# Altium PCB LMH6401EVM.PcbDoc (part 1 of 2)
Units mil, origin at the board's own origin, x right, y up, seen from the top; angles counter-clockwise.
Board outline 1307 x 2660 mil, 6 copper layers (Top Layer L1, Layer 2 GND L2, Layer 3 V+ L3, Layer 4 V- L4, Layer 5 GND L5, Bottom Layer L6), stack 56.6 mil thick; 69 components, 33 nets, 203 pads, 373 vias.
Unrouted connection lines stored in the file: 2.
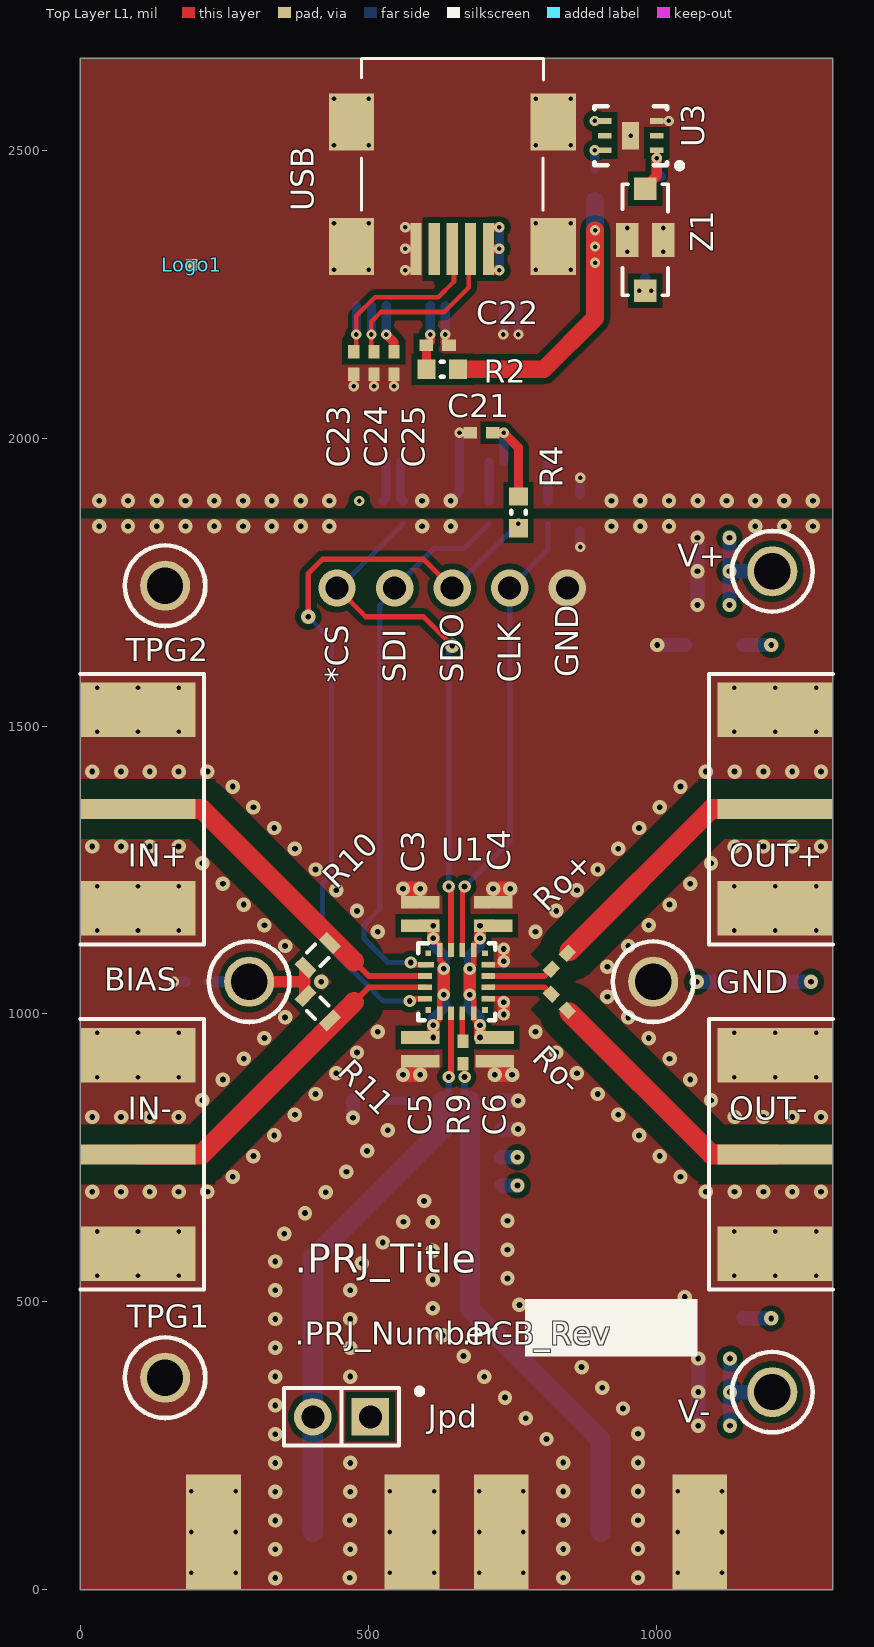
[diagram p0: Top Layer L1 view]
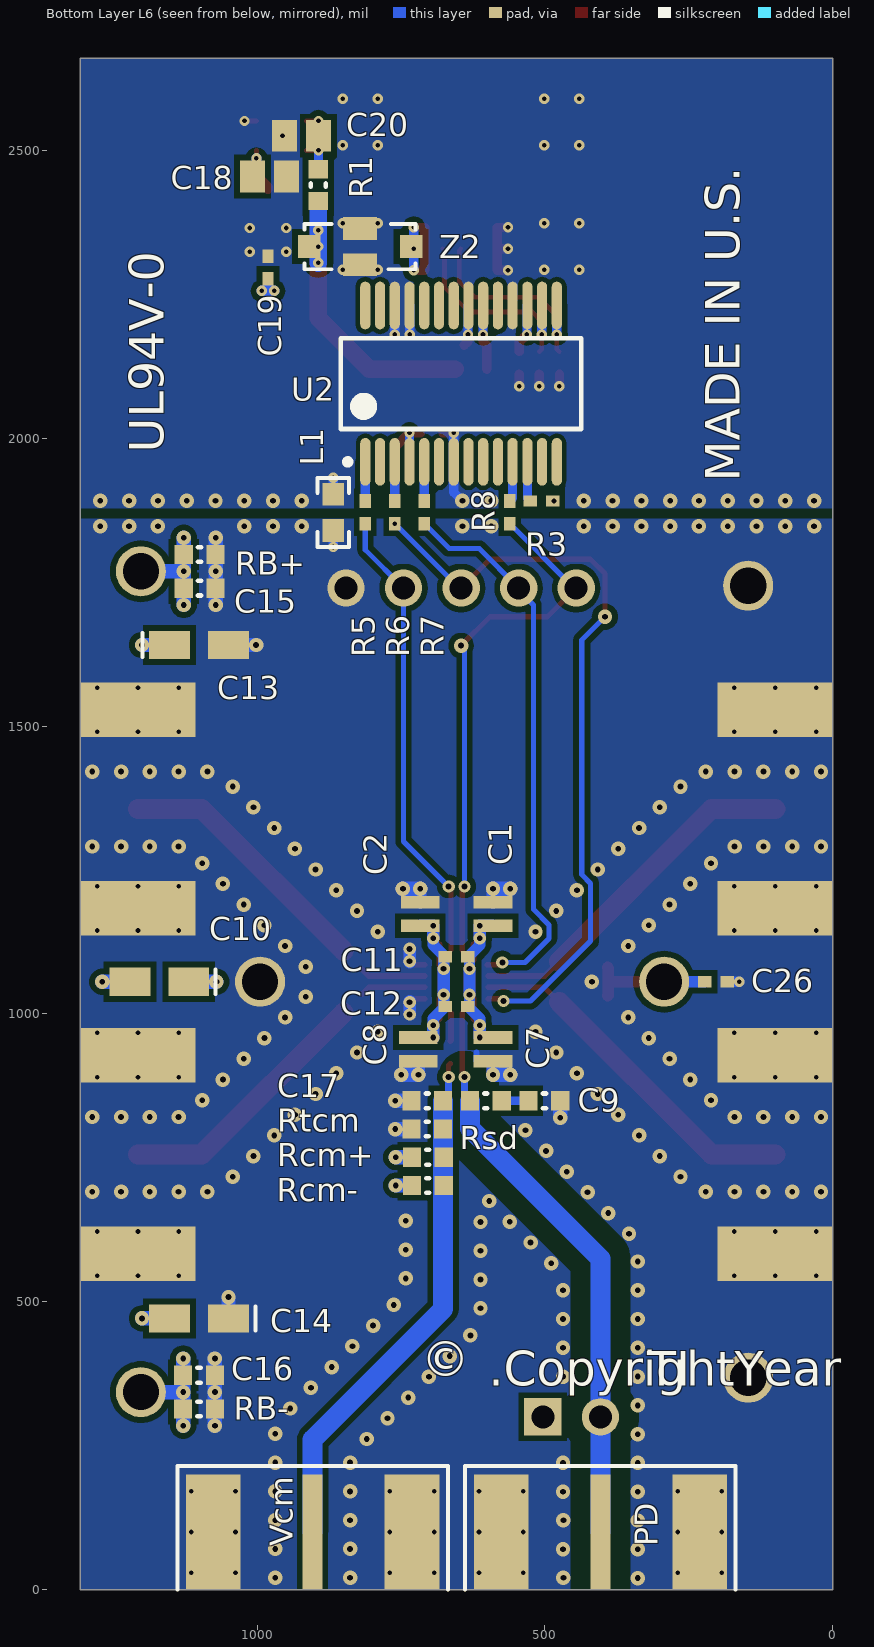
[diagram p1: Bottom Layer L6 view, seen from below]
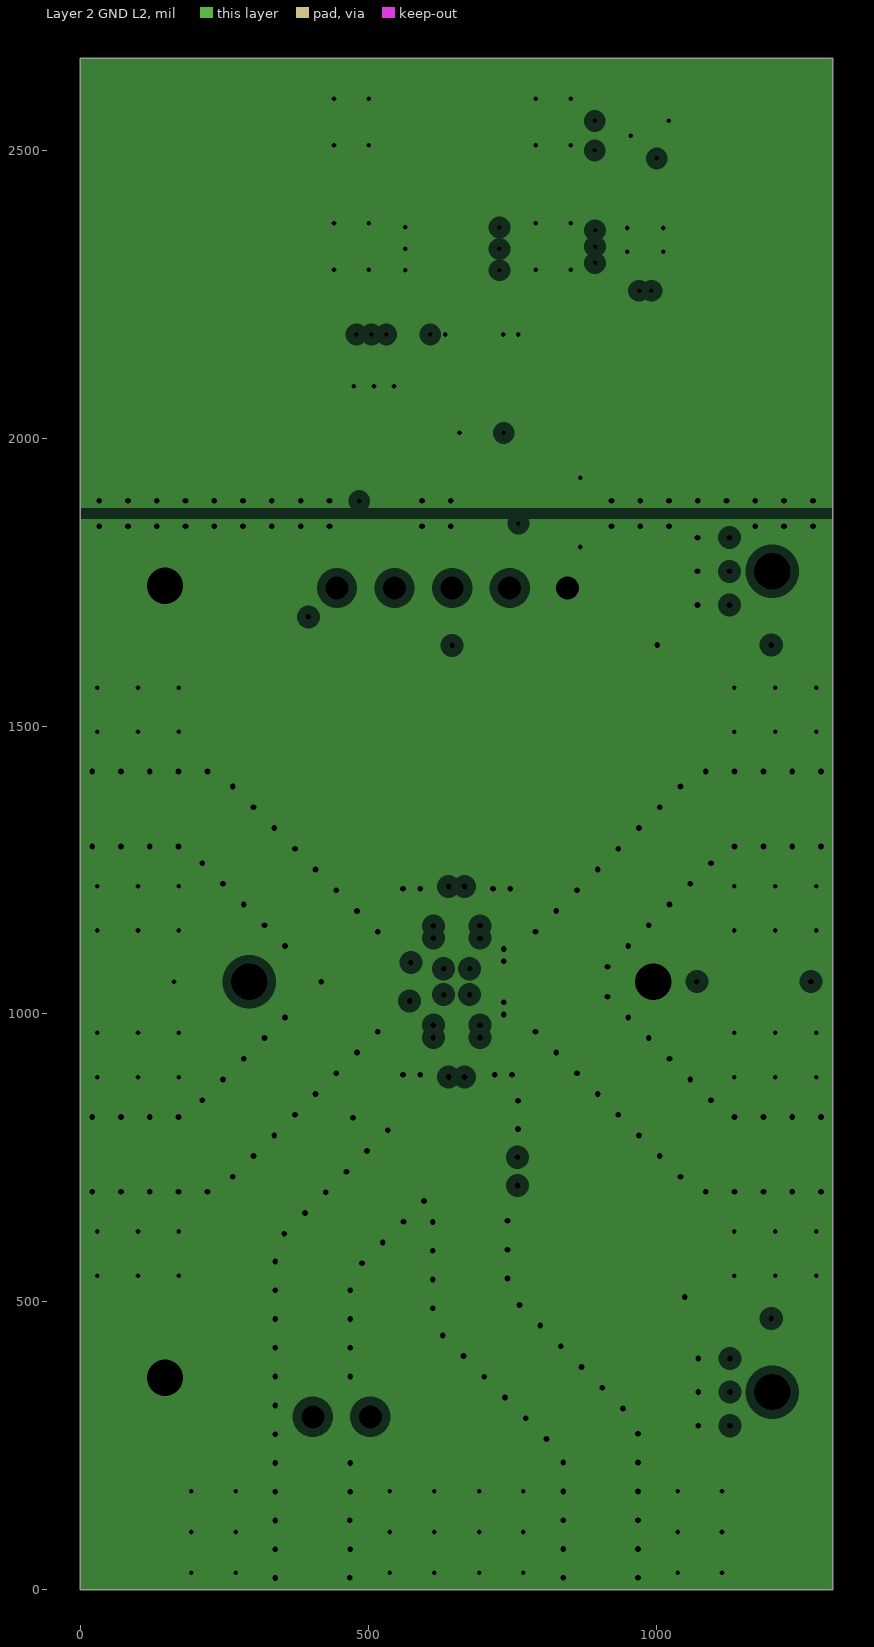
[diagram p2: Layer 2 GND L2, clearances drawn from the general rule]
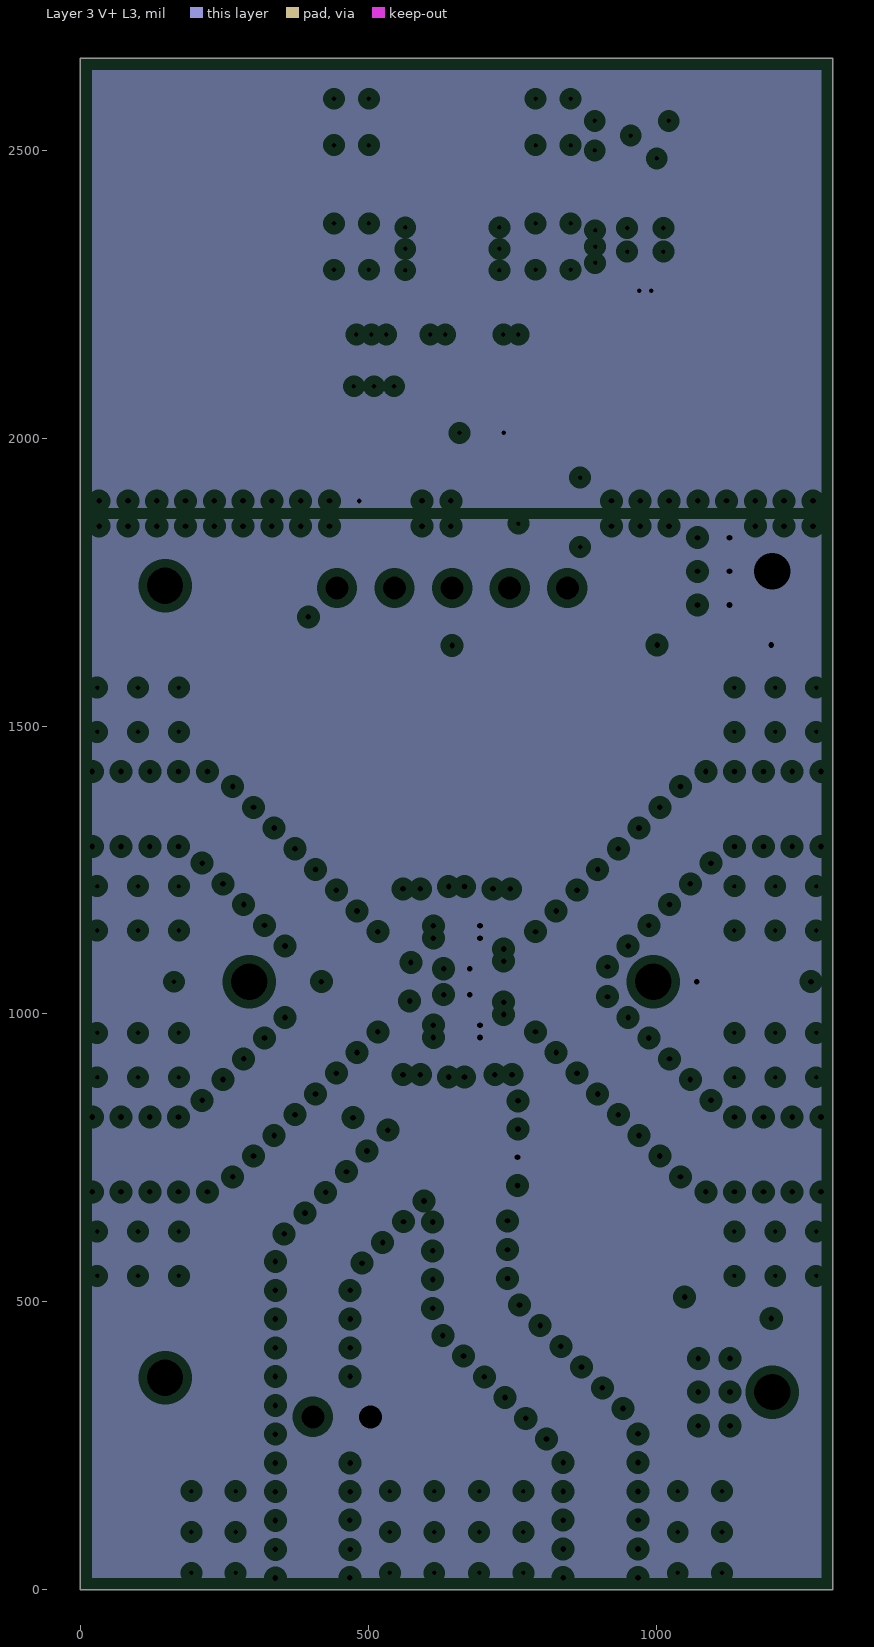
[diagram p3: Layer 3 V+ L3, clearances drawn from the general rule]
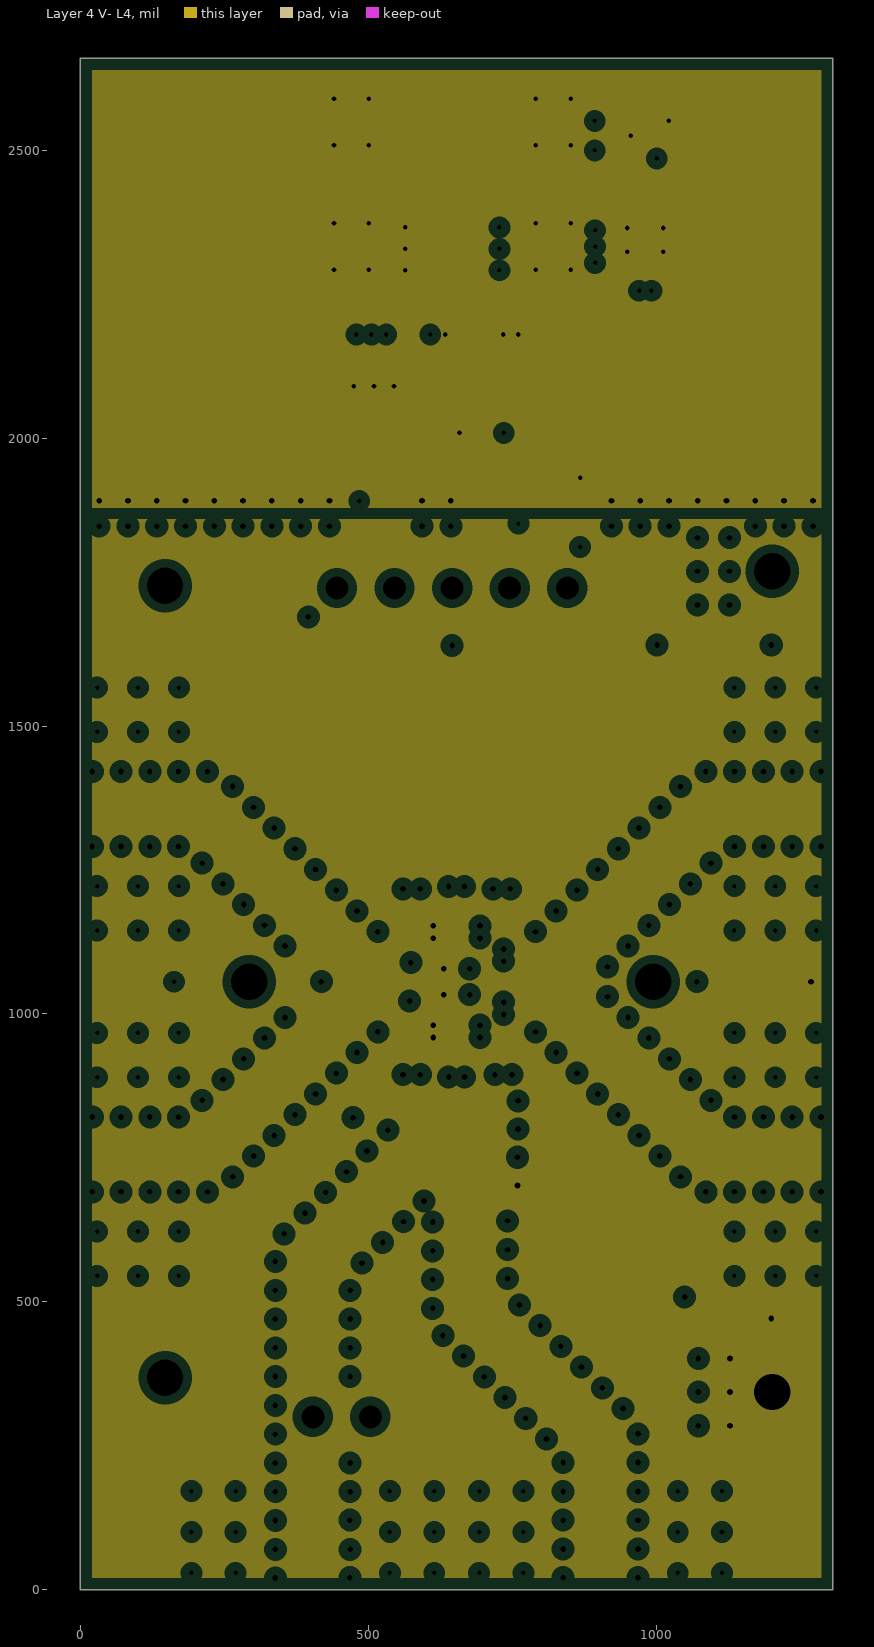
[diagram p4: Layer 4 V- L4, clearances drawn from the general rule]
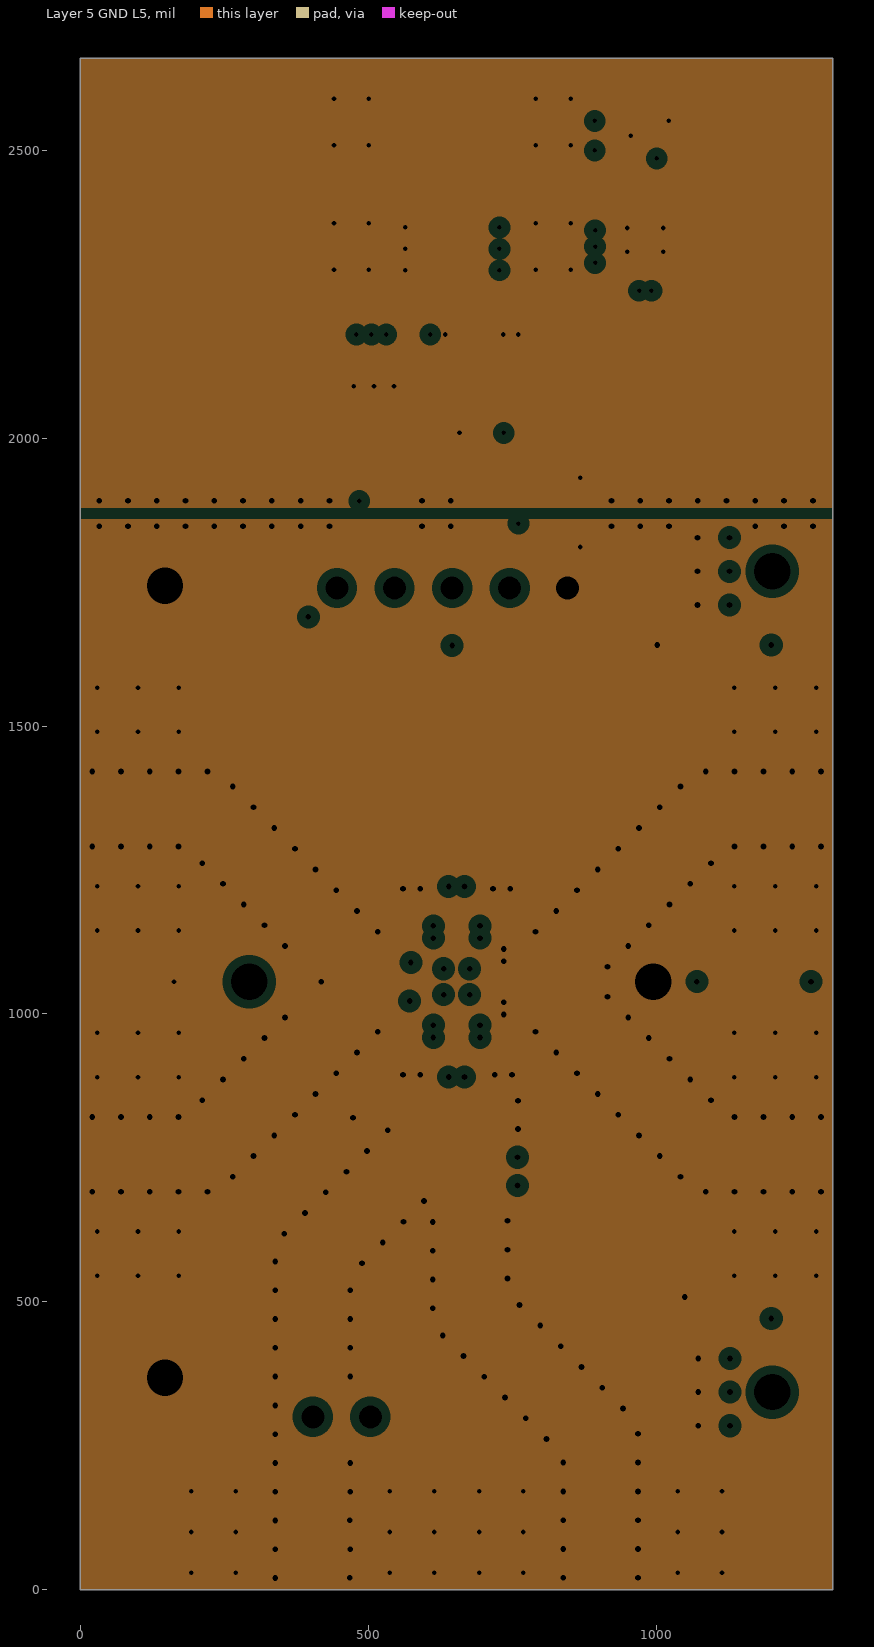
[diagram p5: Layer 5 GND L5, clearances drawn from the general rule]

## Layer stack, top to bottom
Top Layer L1: signal copper 1.4
Dielectric: core 16.6, Rogers RO4350, Dk 3.66
Layer 2 GND L2: plane copper 1.4, net (Multiple Nets)
Dielectric: prepreg 5, FR406, Dk 4.8
Layer 3 V+ L3: plane copper 1.4, net (Multiple Nets)
Dielectric: core 5, FR406, Dk 4.8
Layer 4 V- L4: plane copper 1.4, net (Multiple Nets)
Dielectric: prepreg 5, FR406, Dk 4.8
Layer 5 GND L5: plane copper 1.4, net (Multiple Nets)
Dielectric: core 16.6, FR406, Dk 4.8
Bottom Layer L6: signal copper 1.4

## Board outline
0,0 1307,0 1307,2660 0,2660

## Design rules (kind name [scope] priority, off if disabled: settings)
AcuteAngle [All] p1: minimum=4.50000000000000E+0001 checktracksonly=FALSE
AssemblyTestPointUsage [All] p1: valid=2
Clearance Clearance_2 [(InNamedPolygon('Bottom Layer L6-GND')) vs InNet('NetJpd_2')] p1: gap=35
Clearance Clearance_1 [InNamedPolygon('Top Layer L1-GND') vs (InNet('NetIN+_1') OR InNet('NetIN-_1') OR InNet('NetOUT-_1') OR InNet('NetOUT+_1') OR InNet('NetRtcm_1'))] p2: gap=35
Clearance Clearance_U2 [InComponent('U2')] p3: gap=7.87
Clearance Clearance_BoardEdge_MountingHoles [OnCopper and InComponentClass('Mounting Holes') vs IsKeepOut] p4: gap=40
Clearance Clearance_BoardEdge_Poly [OnCopper and InPoly vs IsKeepOut] p5: gap=25
Clearance Clearance_BoardEdge [OnCopper and Not InComponentClass('Logo') and not InComponentClass('FiducialMark') and not InRegion(1000,500,4000,800) and Not IsKeepout vs IsKeepOut] p6: gap=75
Clearance Clearance_Poly [InPolygon] p7: gap=10
Clearance [All] p8: gap=5
ComponentClearance ComponentClearance_1 [HasFootprint ('Emerson_142-0701-851*') or HasFootprint ('Keystone_1902C*') or HasFootprint ('NY PMS 440 0025 PH*') or HasFootprint ('Fiducial10-20*') vs HasFootprint ('Emerson_142-0701-851*') or HasFootprint ('Keystone_1902C*') or HasFootprint ('NY PMS 440 0025 PH*') or HasFootprint ('Fiducial10-20*')] p1: gap=0 collisioncheckmode=3 verticalgap=10 showdistances=FALSE
ComponentClearance ComponentClearance_Shunt [InComponentClass('Header') vs InComponentClass('Shunt')] p2: gap=0 collisioncheckmode=3 verticalgap=0 showdistances=FALSE
ComponentClearance ComponentClearance_Logo [InComponentClass('Logo')] p3: gap=50 collisioncheckmode=3 verticalgap=10 showdistances=FALSE
ComponentClearance ComponentClearance_ScrewToNut [(HasFootprint('NY PMS 440 0025 PH')) vs (HasFootprint('Keystone_1902C'))] p4: gap=5 collisioncheckmode=3 verticalgap=10 showdistances=FALSE
ComponentClearance ComponentClearance_MountingHoles [InComponentClass('Mounting Holes')] p5: gap=250 collisioncheckmode=3 verticalgap=100000 showdistances=FALSE
ComponentClearance ComponentClearance_SmallPassives [HasFootprint('0201*') or HasFootprint('0402*') or HasFootprint('0508') or HasFootprint('0603*') or HasFootprint('0612') or HasFootprint('0805*') or HasFootprint('0815*') or HasFootprint('0830*') or HasFootprint('1206*') or HasFootprint('1210*') or HasFootprint('1808*') or HasFootprint('1812*') or HasFootprint('1825*') or HasFootprint('2010*') or HasFootprint('2220*') or HasFootprint('2225*') or HasFootprint('2512*') or HasFootprint('2728*') or HasFootprint('3518*') or HasFootprint('FIL_NFM41P*') or HasFootprint('SDB06A*') or HasFootprint('0306*') or HasFootprint('RMZ0016A*') vs HasFootprint('0201*') or HasFootprint('0402*') or HasFootprint('0508') or HasFootprint('0603*') or HasFootprint('0612') or HasFootprint('0805*') or HasFootprint('0815*') or HasFootprint('0830*') or HasFootprint('1206*') or HasFootprint('1210*') or HasFootprint('1808*') or HasFootprint('1812*') or HasFootprint('1825*') or HasFootprint('2010*') or HasFootprint('2220*') or HasFootprint('2225*') or HasFootprint('2512*') or HasFootprint('2728*') or HasFootprint('3518*') or HasFootprint('FIL_NFM41P*') or HasFootprint('SDB06A*') or HasFootprint('0306*') or HasFootprint('RMZ0016A*')] p6: gap=10 collisioncheckmode=3 verticalgap=10 showdistances=FALSE
ComponentClearance ComponentClearance_THtoSMT [IsThruComponent vs IsSMTComponent] p7: gap=10 collisioncheckmode=3 verticalgap=0 showdistances=FALSE
ComponentClearance ComponentClearance_THtoTH [IsThruComponent vs IsThruComponent] p8: gap=75 collisioncheckmode=3 verticalgap=30 showdistances=FALSE
ComponentClearance [All] p9: gap=40 collisioncheckmode=3 verticalgap=10 showdistances=FALSE
DiffPairsRouting [All] p1: maxlimit=100 minlimit=10 mostfreqgap=10 maxuncoupledlength=1000
FabricationTestPointUsage TestPointUsage [All] p1: valid=2 allowmultiple=FALSE
FabricationTestpoint Testpoint [All] p1: side=3 testpointundercomponent=TRUE minsize=40 maxsize=100 preferedsize=60 minholesize=0 maxholesize=40 preferedholesize=32 testpointgrid=1 allowsidetop=TRUE allowsidebottom=TRUE usegrid=TRUE gridtolerance=0.01
FanoutControl Fanout_LCC [IsLCC] p1: bgadir=Out bgaviamode=Centered fanoutstyle=Auto fanoutdirection=Alternating viagrid=1 // Fanout_LCC (Default Rule)
FanoutControl Fanout_BGA [IsBGA] p2: bgadir=Out bgaviamode=Centered fanoutstyle=Auto fanoutdirection=Alternating viagrid=1 // Fanout_BGA (Default Rule)
FanoutControl Fanout_Default [All] p4: bgadir=Out bgaviamode=Centered fanoutstyle=Auto fanoutdirection=Alternating viagrid=1 // Fanout_Default (Default Rule)
FanoutControl Fanout_Small [(CompPinCount < 5)] p5: bgadir=Out bgaviamode=Centered fanoutstyle=Auto fanoutdirection=OutThenIn viagrid=1 // Fanout_Small (Default Rule)
HoleSize [All] p1: absolutevalues=TRUE maxlimit=251 minlimit=8 maxpercent=80.000 minpercent=20.000
MinimumAnnularRing MinimumAnnularRing_ThermalPadVias [IsVia and InAnyComponent] p1: minimumring=5
MinimumAnnularRing [All] p2: minimumring=5
MinimumSolderMaskSliver MinimumSolderMaskSliver_Logo [InComponentClass('Logo') vs InComponentClass('Logo')] p1: minsoldermaskwidth=0.7
MinimumSolderMaskSliver [All] p2: minsoldermaskwidth=3.84
PlaneClearance [All] p1: clearance=15
PlaneConnect [All] p1: planeconnectstyle=Direct reliefexpansion=10 reliefentries=4 reliefconductorwidth=10 reliefairgap=10
PolygonConnect [All] p1: connectstyle=Direct reliefconductorwidth=10 reliefentries=4 polygonreliefangle="90 Angle" airgapwidth=10
RoutingVias ThermalPadVias [IsVia and InAnyComponent] p1: holewidth=7.87 width=19.68 viastyle="Through Hole" minholewidth=8 minwidth=18 maxholewidth=12.99 maxwidth=23.62
RoutingVias [All] p2: holewidth=16 width=34 viastyle="Through Hole" minholewidth=8 minwidth=18 maxholewidth=40 maxwidth=65
SMDToCorner [All] p1: distance=30000
SilkToSilkClearance [All] p1: silktosilkclearance=5
SilkscreenOverComponentPads [IsPad] p1: minsilkscreentomaskgap=5
SolderMaskExpansion [All] p1: expansion=1.97
Width [All] p1: maxlimit=100 minlimit=6 preferedwidth=10 checkconnectedcopper=TRUE
13 further rules are at their usual default settings.

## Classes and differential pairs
component class Header: Jpd
component class AssemblyNote: ZZ2 ZZ3 ZZ4
component class Logo: Logo1

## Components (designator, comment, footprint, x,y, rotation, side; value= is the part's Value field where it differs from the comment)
BIAS "5012" Keystone5012 293,1056 r0 top
C1 "LLL185R71E103MA01L" 0306 590.34,1173.48 r270 bottom
C2 "LLL185R71E103MA01L" 0306 716.87,1173.48 r90 bottom
C3 "LLL185R71H222MA01L" 0306 590.34,1173.48 r90 top
C4 "LLL185R71H222MA01L" 0306 716.87,1173.48 r270 top
C5 "LLL185R71H222MA01L" 0306 590.34,938.52 r270 top
C6 "LLL185R71H222MA01L" 0306 719.87,938.52 r90 top
C7 "LLL185R71E103MA01L" 0306 590.34,938.52 r90 bottom
C8 "LLL185R71E103MA01L" 0306 719.87,938.52 r270 bottom
C9 "GRM188R71C103KA01D" 0603L 501,849 r180 bottom
C10 "TPSA106K010R0900" 3216-18 1170,1056 r0 bottom
C11 "C1005X5R1A104K" 0402L 653.6,1099.1 r0 bottom
C12 "C1005X5R1A104K" 0402L 653.6,1012.9 r0 bottom
C13 "TPSA106K010R0900" 3216-18 1101,1641 r180 bottom
C14 "TPSA106K010R0900" 3216-18 1101,471 r0 bottom
C15 "Used in BOM report" 0603L 1100,1739.77 r180 bottom
C16 "Used in BOM report" 0603L 1101,372.23 r180 bottom
C17 "GRM188R71C103KA01D" 0603L 704.5,849 r0 bottom
C18 "EMK212BJ106KG-T" 0805L 978.51,2455 r180 bottom
C19 "C1005X5R1A104K" 0402L 981.25,2296.91 r270 bottom
C20 "EMK212BJ106KG-T" 0805L 923.06,2525.9 r0 bottom
C21 "C1005X7R1C103K" 0402L 696.93,2009.51 r180 top
C22 "C1005X7R1C103K" 0402L 620.66,2161.64 r0 top
C23 "GRM1555C1H470JZ01" 0402L 474.96,2131 r270 top
C24 "GRM1555C1H470JZ01" 0402L 509.96,2131 r270 top
C25 "C1005X5R1A104K" 0402L 544.75,2131 r90 top
C26 "C1005X5R1A104K" 0402L 203,1056 r0 bottom
GND "5011" Keystone5011 995,1056 r0 top
IN+ "142-0701-851" Emerson_142-0701-851#1 100,1356 r90 top
IN- "142-0701-851" Emerson_142-0701-851#1 100,756 r90 top
Jpd "TSW-102-07-G-S" TSW-102-07-G-S 453.6,300 r180 top
L1 "BLM18SG331TN1D" 0603 868,1871.5 r90 bottom
Logo1 "Texas Instruments" TI_Stacked_SolderMask_Small_Vertical 192,2300 r0 top
OUT+ "142-0701-851" Emerson_142-0701-851#1 1207,1356 r270 top
OUT- "142-0701-851" Emerson_142-0701-851#1 1207,756 r270 top
PD "142-0701-851" Emerson_142-0701-851#2 403.6,100 r0 bottom
R1 "CRCW06030000Z0EA" 0603L 894.03,2440 r270 bottom
R2 "CRCW06030000Z0EA" 0603L 628.53,2120 r180 top
R3 "CRCW040210K0FKED" 0402L 505.91,1891.18 r180 bottom
R4 "CRCW0603301RFKEA" 0603L 760.91,1871.5 r90 top
R5 "CRCW040222R1FKED" 0402L 812.09,1871.5 r90 bottom
R6 "CRCW040222R1FKED" 0402L 760.91,1871.5 r90 bottom
R7 "CRCW040222R1FKED" 0402L 709.72,1871.5 r90 bottom
R8 "CRCW040222R1FKED" 0402L 561.18,1871.5 r90 bottom
R9 "ERJ-2GE0R00X" 0402L 664.5,933 r90 top
R10 "CRCW060310K0FKEA" 0603S 412.26,1102 r45 top
R11 "CRCW060310K0FKEA" 0603S 412.26,1010 r135 top
RB+ "Used in BOM report" 0603L 1100,1798.23 r0 bottom
RB- "Used in BOM report" 0603L 1101,313.77 r180 bottom
Rcm+ "CRCW06031K00FKEA" 0603L 703.5,751 r0 bottom
Rcm- "CRCW06031K00FKEA" 0603L 703.5,702 r180 bottom
Ro+ "CRCW040240R2FKED" 0402L 831.93,1091.61 r45 top
Ro- "CRCW040240R2FKED" 0402L 831.93,1020.39 r315 top
Rsd "CRCW060349R9FKEA" 0603L 602.71,849 r0 bottom
Rtcm "Used in BOM report" 0603L 704.5,800 r0 bottom
TPG1 "5011" Keystone5011 147,368 r0 top
TPG2 "5011" Keystone5011 147,1744 r0 top
U1 "LMH6401IRMZR" RMZ0016A 653.6,1056 r0 top
U2 "FT245RL" SSOP28_N 645.75,2095 r90 bottom
U3 "LP5900SD-1.8/NOPB" SDB06A 956.02,2525.9 r180 top
USB "651-305-142-821" CONN_USB-MINI-AB-651-305-142-821 646,2439.53 r180 top
V+ "5010" Keystone5010 1202,1769 r0 top
V- "5014" Keystone5014 1202,343 r0 top
Vcm "142-0701-851" Emerson_142-0701-851#2 903.6,100 r0 bottom
Z1 "NFM41PC204F1H3L" FIL_NFM41P 981.25,2345 r90 top
Z2 "NFM41PC204F1H3L" FIL_NFM41P 821.2,2333.23 r180 bottom
ZZ2 "These assemblies are ESD sensitive, ESD precautions shall be observed." AssemblyNote 185,3829.11 r0 top
ZZ3 "These assemblies must be clean and free from flux and all contaminants. Use of no clean flux is not acceptable." AssemblyNote 185,3740.56 r0 top
ZZ4 "These assemblies must comply with workmanship standards IPC-A-610 Class 2, unless otherwise specified." AssemblyNote 185,3652 r0 top

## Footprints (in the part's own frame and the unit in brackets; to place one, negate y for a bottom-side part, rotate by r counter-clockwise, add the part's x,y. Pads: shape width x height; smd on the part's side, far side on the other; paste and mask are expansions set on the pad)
0306 [mil] "bxl footprint"
  rect 22x67 smd: 1(-20.5,0) 2(20.5,0)
  body extent -17,-33 17,33, height 24
0402L [mm] "0402 from SM-752 data"
  rect 0.6x0.5 smd: 1(-0.5,0) 2(0.5,0)
  body extent -0.55,-0.3 0.55,0.3, height 0.6
0603 [mm] "0603 from SM-752 data"
  rect 1x0.95 smd: 1(-0.8,0) 2(0.8,0)
  silkscreen extent -1.52,-0.69 1.52,0.69, body extent -0.87,-0.47 0.87,0.47, height 0.85
0603L [mm] "0603 from SM-752 data"
  rect 0.8x0.85 smd: 1(-0.7,0) 2(0.7,0)
  silkscreen extent -0.07,-0.33 0.07,0.33, body extent -0.87,-0.47 0.87,0.47, height 0.85
0603S [mil]
  rect 20x35 smd: 1(-30,0) 2(30,0)
  silkscreen extent -10,-17 10,17, body extent -34,-19 34,19, height 33
0805L [mm] "0805 from SM-752 data"
  rect 1.1x1.4 smd: 1(-0.75,0) 2(0.75,0)
  body extent -1.1,-0.72 1.1,0.72, height 1.1
3216-18 [mm] "Medium density IPC, based on Kemet T495 dimensions"
  rect 1.8x1.25 smd: 1(-1.3,0) 2(1.3,0)
  silkscreen extent -2.49,-0.54 -2.49,0.54, body extent -1.7,-0.9 1.7,0.9, height 1.8
AssemblyNote [mil] "Assembly Note"
CONN_USB-MINI-AB-651-305-142-821 [mm] "WE-USB2-MINI-AB TYPE"
  rect 0.5x2.3 smd: 1(-1.6,2.8) 2(-0.8,2.8) 3(0,2.8) 4(0.8,2.8) 5(1.6,2.8)
  rect 2x2.5 smd: 6(4.45,2.7) 7(4.45,-2.8) 8(-4.45,-2.8) 9(-4.45,2.7)
  silkscreen extent -4.03,-5.6 4,1.1, body extent -4.95,-5.72 4.95,3.68, height 4.12
Emerson_142-0701-851#1 [mil] "Johnson Components"
  rect 35x200 smd mask+3: 1(0,0)
  rect 95x200 smd: 2(-172.5,0) 3(172.5,0)
  rect 95x200 smd far side: 4(172.5,0) 5(-172.5,0)
  silkscreen extent -235,-115 235,100, body extent -190,-95 190,487, height 155
Emerson_142-0701-851#2 [mil] "Johnson Components"
  rect 35x200 smd: 1(0,0)
  rect 95x200 smd: 2(-172.5,0) 3(172.5,0)
  rect 95x200 smd far side: 4(172.5,0) 5(-172.5,0)
  silkscreen extent -235,-115 235,100, body extent -190,-95 190,487, height 155
FIL_NFM41P [mm] "FILTER LC HIGH FREQ .2UF 1806"
  rect 1x1 smd: 1(-2.25,0) 3(2.25,0)
  rect 1.5x1 smd: 2(0,0.8) 2(0,-0.8)
  silkscreen extent -2.45,-1 2.45,1, body extent -2.4,-0.95 2.4,0.95, height 1.2
Keystone5010 [mil] "Keystone Multipurpose loops"
  round 87 hole 63: 1(0,0)
  silkscreen extent -70,-70 70,70, body extent -63,-63 63,62, height 319
Keystone5011 [mil] "Keystone Multipurpose loops"
  round 87 hole 63: 1(0,0)
  silkscreen extent -70,-70 70,70, body extent -63,-63 63,62, height 319
Keystone5012 [mil] "Keystone Multipurpose loops"
  round 87 hole 63: 1(0,0)
  silkscreen extent -70,-70 70,70, body extent -63,-63 63,62, height 319
Keystone5014 [mil] "Keystone Multipurpose loops"
  round 87 hole 63: 1(0,0)
  silkscreen extent -70,-70 70,70, body extent -63,-63 63,62, height 319
RMZ0016A [mm] "QFN, 16-Leads, Body 3.0x3.0 mm, Pitch 0.5mm"
  rrect0% 0.7x0.25 smd paste+0 mask+0.062: 1(-1.35,0.75)
  rrect0% 0.6x0.25 smd paste+0 mask+0.062: 2(-1.4,0.25) 3(-1.4,-0.25) 4(-1.4,-0.75) 9(1.4,-0.75) 10(1.4,-0.25) 11(1.4,0.25) 12(1.4,0.75)
  rrect0% 0.25x0.6 smd paste+0 mask+0.062: 5(-0.75,-1.4) 6(-0.25,-1.4) 7(0.25,-1.4) 8(0.75,-1.4) 13(0.75,1.4) 14(0.25,1.4) 15(-0.25,1.4) 16(-0.75,1.4)
  rrect0% 0.25x0.25 smd paste+0 mask+0.062: ""(-1.25,-1.25) ""(-1.25,1.25) ""(1.25,-1.25) ""(1.25,1.25)
  silkscreen extent -1.7,-1.7 1.7,1.7, body extent -1.55,-1.55 1.55,1.55, height 0.65
SDB06A [mm] "SON, 6-Leads, Body 2.2x2.5mm, Pitch 0.65mm, NSC Recommended (SC-70 Land)"
  rect 0.6x0.25 smd paste-0.125 mask+0.051: 1(-1.15,0.65) 2(-1.15,0) 3(-1.15,-0.65) 4(1.15,-0.65) 5(1.15,0) 6(1.15,0.65)
  rect 0.75x1.2 smd paste-0.6 mask+0.051: 7(0,0)
  silkscreen extent -2.28,-1.3 1.6,1.45, body extent -1.3,-1.15 1.3,1.15, height 0.8
SSOP28_N [mm] "SOP, 28-Leads, Body 10.2x5.3mm, Pitch 0.65mm, IPC Medium Density"
  oval 2.1x0.45 smd: 1(-3.45,4.225) 2(-3.45,3.575) 3(-3.45,2.925) 4(-3.45,2.275) 5(-3.45,1.625) 6(-3.45,0.975) 7(-3.45,0.325) 8(-3.45,-0.325) 9(-3.45,-0.975) 10(-3.45,-1.625) 11(-3.45,-2.275) 12(-3.45,-2.925) 13(-3.45,-3.575) 14(-3.45,-4.225) 15(3.45,-4.225) 16(3.45,-3.575) 17(3.45,-2.925) 18(3.45,-2.275) 19(3.45,-1.625) 20(3.45,-0.975) 21(3.45,-0.325) 22(3.45,0.325) 23(3.45,0.975) 24(3.45,1.625) 25(3.45,2.275) 26(3.45,2.925) 27(3.45,3.575) 28(3.45,4.225)
  silkscreen extent -3.57,-5.3 2,5.3, body extent -2.7,-5.3 2.7,5.3, height 2
TI_Stacked_SolderMask_Small_Vertical [mil]
  rect 20x20 smd paste-125 mask-125: 0(1.25,1.75)
TSW-102-07-G-S [mm] "Samtec 100mil, 1x2, 230 mil above insulator"
  rect 1.65x1.65 hole 1.016 mask+0: 1(-1.27,0)
  round 1.65 hole 1.016 mask+0: 2(1.27,0)
  silkscreen extent -3.57,-1.27 2.54,1.27, body extent -2.54,-1.27 2.54,1.27, height 8.38

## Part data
BIAS: "Test Point, Multipurpose, White, TH"
C1 C2 C7 C8: "CAP, CERM, 0.01uF, 25V, +/-20%, X7R, 0306"
C3 C4 C5 C6: "CAP, CERM, 2200pF, 50V, +/-20%, X7R, 0306"
C9 C17: "CAP, CERM, 0.01uF, 16V, +/-10%, X7R, 0603"
C10 C13 C14: "CAP, TA, 10uF, 10V, +/-10%, 0.9 ohm, SMD"
C11 C12 C19 C25 C26: "CAP, CERM, 0.1uF, 10V, +/-10%, X5R, 0402"
C15 C16: library part Capacitor, "CAP, CERM, xxxF, xxV, [TempCo], xx%, [PackageReference]"
C18 C20: "CAP, CERM, 10uF, 16V, +/-10%, X5R, 0805"
C21 C22: "CAP, CERM, 0.01uF, 16V, +/-10%, X7R, 0402"
C23 C24: "CAP, CERM, 47pF, 50V, +/-5%, C0G/NP0, 0402"
GND TPG1 TPG2: "Test Point, TH, Multipurpose, Black"
IN+ IN- OUT+ OUT- PD Vcm: "Connector, SMT, End launch SMA 50 ohm"
Jpd: "Header, TH, 100mil, 2x1, Gold plated, 230 mil above insulator"
L1: "1.5A Ferrite Bead, 330 ohm @ 100MHz, SMD"
Logo1: library part TI_Logo, "Texas Instrument Corporate Signature"
R1 R2: "RES, 0 ohm, 5%, 0.1W, 0603"
R3: "RES, 10.0k ohm, 1%, 0.063W, 0402"
R4: "RES, 301 ohm, 1%, 0.1W, 0603"
R5 R6 R7 R8: "RES, 22.1 ohm, 1%, 0.063W, 0402"
R9: "RES, 0 ohm, 5%, 0.063W, 0402"
R10 R11: "RES, 10.0k ohm, 1%, 0.1W, 0603"
RB+ RB- Rtcm: library part Resistor, "RES, xxx ohm, x%, xW, [PackageReference]"
Rcm+ Rcm-: "RES, 1.00k ohm, 1%, 0.1W, 0603"
Ro+ Ro-: "RES, 40.2 ohm, 1%, 0.063W, 0402"
Rsd: "RES, 49.9 ohm, 1%, 0.1W, 0603"
U1: "5 GHz Ultra Wideband Digital Variable Gain Amplifier, RMZ0016A"
U2: "USB FIFO IC, 28SSOP"
U3: "Ultra Low Noise, 150mA Linear Regulator for RF/Analog Circuits Requires No Bypass Capacitor, 6-pin LLP, Pb-Free"
USB: "MINI USB 2.0 SMT TYPE AB 5 CONTACTS R/A, SMD"
V+: "Test Point, TH, Multipurpose, Red"
V-: "Test Point, Multipurpose, Yellow, TH"
Z1 Z2: "Filter, LC, 0.2uF, 1806, SMT"
ZZ2 ZZ3 ZZ4: library part AssemblyNote

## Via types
v1: diameter 25, hole 10, Top Layer L1 to Bottom Layer L6, tented both sides, 221 vias
v2: diameter 18, hole 8, Top Layer L1 to Bottom Layer L6, tented top, 73 vias
v3: diameter 18, hole 8, Top Layer L1 to Bottom Layer L6, tented both sides, 52 vias
v4: diameter 21.46, hole 10, Top Layer L1 to Bottom Layer L6, tented both sides, 22 vias
v5: diameter 64.96, hole 40, Top Layer L1 to Bottom Layer L6, 5 vias

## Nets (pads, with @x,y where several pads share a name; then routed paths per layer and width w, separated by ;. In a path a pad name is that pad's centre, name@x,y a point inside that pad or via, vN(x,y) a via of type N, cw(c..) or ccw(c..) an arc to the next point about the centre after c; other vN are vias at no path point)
\CS: R8.1 U1.15 | length 932.5
  Top Layer L1 w9: v5(445.75,1740) 495.75,1690 595.75,1690 v1(645.75,1640)
  Top Layer L1 w9.84: v4(639.79,1221.48) 643.76,1217.51 U1.15@643.76,1111.12
  Bottom Layer L6 w9: v5@449.37,1740 R8.1@561.18,1851.81 ; v4(639.79,1221.48) 639.79,1634.04 v1(645.75,1640)
CLK: R5.1 U1.14 | length 802.3
  Top Layer L1 w9: U1.14@663.45,1111.12 663.45,1217.51 v4(667.41,1221.48)
  Bottom Layer L6 w9: v4(667.41,1221.48) 745.75,1299.81 v5(745.75,1740) 812.09,1806.34 R5.1@812.09,1851.81
GND: C1.1 C2.2 C3.2 C4.1 C5.2 C6.1 C7.1 C8.2 C9.2 C13.2 C14.1 C15.2 C16.2 C17.2 C26.1 GND.1 IN+.2 IN+.3 IN+.4 IN+.5 IN-.2 IN-.3 IN-.4 IN-.5 L1.1 OUT+.2 OUT+.3 OUT+.4 OUT+.5 OUT-.2 OUT-.3 OUT-.4 OUT-.5 PD.2 PD.3 PD.4 PD.5 RB+.1 RB-.2 Rtcm.2 TPG1.1 TPG2.1 U1.9 U1.12 Vcm.2 Vcm.3 Vcm.4 Vcm.5 | length 1069.1
  Top Layer L1 w9.84: U1.9@708.72,1026.47 729.16,1026.47 v4(735.2,1020.43) ; U1.12@708.72,1085.53 729.16,1085.53 v4(735.2,1091.57)
  Top Layer L1 w21.46: v4@735.2,999.05 v4(735.2,1020.43) ; v4(735.2,1091.57) v4@735.2,1112.95
  Top Layer L1 w22: v1(590.34,894.52) C5.2@590.34,918.02 ; C3.2@590.34,1193.98 v1(590.34,1217.48) ; C4.1@716.87,1193.98 v1(716.87,1217.48) ; v1(719.87,894.52) C6.1@719.87,918.02
  Top Layer L1 w25: v1(560.34,894.52) v1(590.34,894.52) ; v1(560.34,1217.48) v1(590.34,1217.48) ; v1(716.87,1217.48) v1(746.87,1217.48) ; v1(719.87,894.52) v1(749.87,894.52)
  Bottom Layer L6 w10: C7.1@590.34,918.02 618.84,918.02 618.84,933
  Bottom Layer L6 w16: v3(868,1811.32) L1.1@868,1840
  Bottom Layer L6 w18: v3(162.5,1056) C26.1@183.32,1056
  Bottom Layer L6 w21.46: v4@735.2,1001.13 v4@735.2,1022.5 ; v4@735.2,1089.58 v4@735.2,1110.96
  Bottom Layer L6 w22: v1(590.34,894.52) C7.1@590.34,918.02 ; C1.1@590.34,1193.98 v1(590.34,1217.48) ; C2.2@716.87,1193.98 v1(716.87,1217.48) ; v1(719.87,894.52) C8.2@719.87,918.02
  Bottom Layer L6 w25: v1(473.44,819.77) C9.2@473.44,849 ; v1(560.34,894.52) v1(590.34,894.52) ; v1(560.34,1217.48) v1(590.34,1217.48) ; v1(716.87,1217.48) v1(746.87,1217.48) ; v1(719.87,894.52) v1(749.87,894.52) ; Rtcm.2@732.06,800 v1(760.31,800) ; C17.2@732.06,849 v1(760.31,849) ; v1(1001.89,1641) C13.2@1049.82,1641 ; C14.1@1049.82,471 v1(1049.82,508.11) ; v1(1071.95,1710.54) v1(1071.95,1769) v1(1071.95,1827.46) ; v1(1073.44,284.54) v1(1073.44,343) v1(1073.44,401.46)
  other v1: 338.6,19.92 468,20.5 838.6,20.5 968.6,20.5 338.6,69.92 468.6,69.92 838.6,70.5 968.6,70.5 338.6,119.92 468,120.5 838.6,120.5 968.6,120.5 338.6,169.92 468.6,169.92 838.6,170.5 968.6,170.5 338.6,219.92 468.6,219.92 838.6,220.5 968.6,220.5 809.6,261.5 338.6,269.92 968.6,270.5 773.6,297.5 942.6,314.5 338.6,319.92 737.6,333.5 906.6,350.5 701.6,369.5 338.6,369.92 468.6,369.92 870.6,386.5 665.6,405.5 338.6,419.92 468.6,419.92 834.6,422.5 629.6,441.5 798.6,458.5 338.6,469.92 468.6,469.92 611.94,488.52 762.6,494.5 338.6,519.92 468.6,519.92 611.94,538.52 741.94,540.52 489,567 338.6,569.92 611.94,588.52 741.94,590.52 525,603 354,618 561,639 611.94,638.52 741.94,640.52 390,654 597,675 426,690 20.5,691 70.5,691 120.5,691 170.5,691 220.5,691 1086.5,691 1136.5,691 1186.5,691 1236.5,691 1286.5,691 264.5,717 1042.5,717 462,726 300.5,753 1006.5,753 498,762 336.5,789 970.5,789 534,798 20.5,821 70.5,821 120.5,821 170.5,821 1136.5,821 1186.5,821 1236.5,821 1286.5,821 372.5,825 934.5,825 211.5,850 1095.5,850 408.5,861 898.5,861 247.5,886 1059.5,886 444.5,897 862.5,897 283.5,922 1023.5,922 480.5,933 826.5,933 319.5,958 987.5,958 516.5,969 790.5,969 355.5,994 951.5,994 915.5,1030 418.5,1056 915.5,1082 355.5,1118 951.5,1118 516.5,1143 790.5,1143 319.5,1154 987.5,1154 480.5,1179 826.5,1179 283.5,1190 1023.5,1190 444.5,1215 862.5,1215 247.5,1226 1059.5,1226 408.5,1251 898.5,1251 211.5,1262 1095.5,1262 372.5,1287 934.5,1287 20.5,1291 70.5,1291 120.5,1291 170.5,1291 1136.5,1291 1186.5,1291 1236.5,1291 1286.5,1291 336.5,1323 970.5,1323 300.5,1359 1006.5,1359 264.5,1395 1042.5,1395 20.5,1421 70.5,1421 120.5,1421 170.5,1421 220.5,1421 1086.5,1421 1136.5,1421 1186.5,1421 1236.5,1421 1286.5,1421 32.5,1847.5 82.5,1847.5 132.5,1847.5 182.5,1847.5 232.5,1847.5 282.5,1847.5 332.5,1847.5 382.5,1847.5 432.5,1847.5 593.5,1847.5 643.5,1847.5 922.5,1847.5 972.5,1847.5 1022.5,1847.5 1172.5,1847.5 1222.5,1847.5 1272.5,1847.5
  other v2: 192.6,29 269.6,29 537.6,29 614.6,29 692.6,29 769.6,29 1037.6,29 1114.6,29 192.6,100 269.6,100 537.6,100 614.6,100 692.6,100 769.6,100 1037.6,100 1114.6,100 192.6,171 269.6,171 537.6,171 614.6,171 692.6,171 769.6,171 1037.6,171 1114.6,171 29,545 100,545 171,545 1136,545 1207,545 1278,545 29,622 100,622 171,622 1136,622 1207,622 1278,622 29,890 100,890 171,890 1136,890 1207,890 1278,890 29,967 100,967 171,967 1136,967 1207,967 1278,967 29,1145 100,1145 171,1145 1136,1145 1207,1145 1278,1145 29,1222 100,1222 171,1222 1136,1222 1207,1222 1278,1222 29,1490 100,1490 171,1490 1136,1490 1207,1490 1278,1490 29,1567 100,1567 171,1567 1136,1567 1207,1567 1278,1567
  other v4: 735.2,998.97 735.2,1113.03
  other v5: 845.75,1740
GND2: C18.2 C19.1 C20.2 C21.2 C22.2 C23.2 C24.2 C25.1 L1.2 Logo1.0 U2.7 U2.18 U2.21 U2.25 U2.26 U3.3 U3.7 USB.5 USB.6 USB.7 USB.8 USB.9 Z1.2 Z2.2 | length 558.6
  Top Layer L1 w9: U3.3@1001.29,2551.49 v3(1022.1,2551.49)
  Top Layer L1 w16: v3(474.96,2090.5) C23.2@474.96,2111.31 ; v3(509.96,2090.5) C24.2@509.96,2111.31 ; v3(544.75,2090.5) C25.1@544.75,2111.31 ; v3(564.16,2292.02) 583.01,2292.02 USB.5@583.01,2329.29 ; v3(564.16,2329.29) USB.5@583.01,2329.29 ; v3(564.16,2366.57) 583.01,2366.57 USB.5@583.01,2329.29 ; v3(633.7,2180.49) 633.7,2168.28 C22.2@640.34,2161.64 ; v3(658.54,2009.51) C21.2@677.24,2009.51
  Bottom Layer L6 w16: v3(633.7,2180.49) U2.21@633.7,2230.83 ; v1(643.5,1891.5) 658.54,1906.54 v3(658.54,2009.51) ; v3(734.82,2180.49) U2.25@734.82,2230.83 ; v3(760.91,2180.49) U2.26@760.91,2230.83 ; L1.2@868,1903 v3(868,1931.68)
  other v1: 32.5,1891.5 82.5,1891.5 132.5,1891.5 182.5,1891.5 232.5,1891.5 282.5,1891.5 332.5,1891.5 382.5,1891.5 432.5,1891.5 593.5,1891.5 922.5,1891.5 972.5,1891.5 1022.5,1891.5 1072.5,1891.5 1122.5,1891.5 1172.5,1891.5 1222.5,1891.5 1272.5,1891.5
  other v2: 956.02,2525.9
  other v3: 440.43,2293.02 501.17,2293.02 790.83,2293.02 851.57,2293.02 949.75,2324.47 1012.74,2324.47 949.75,2365.53 1012.74,2365.53 440.43,2373.44 501.17,2373.44 790.83,2373.44 851.57,2373.44 440.43,2509.55 501.17,2509.55 790.83,2509.55 851.57,2509.55 440.43,2589.98 501.17,2589.98 790.83,2589.98 851.57,2589.98
NetBIAS_1: BIAS.1 C26.2 R10.1 R11.2 | length 217.8
  Top Layer L1 w20: BIAS.1@293,1056 390,1056 ; R11.2@391.05,1031.21 390,1032.26 390,1056 ; R10.1@391.04,1080.79 390,1079.74 390,1056
  Bottom Layer L6 w20: C26.2@222.69,1056 BIAS.1@293,1056
NetC9_1: C9.1 Rsd.1 | length 46.6
  Bottom Layer L6 w15: C9.1@528.56,849 Rsd.1@575.15,849
NetC17_1: C17.1 R9.1 Rcm+.1 Rcm-.2 Rtcm.1 Vcm.1 | length 911.9
  Top Layer L1 w9: R9.1@664.5,913.32 667.41,910.4 v4(667.41,890.52)
  Bottom Layer L6 w12: v4(667.41,890.52) 667.41,857.53 C17.1@675.94,849
  Bottom Layer L6 w35: C17.1@676.94,849 Rtcm.1@676.94,800 676.94,487.34 903.6,260.68 Vcm.1@903.6,100
NetC18_1: C18.1 U3.1 Z1.3 | length 109.2
  Top Layer L1 w9: v3(1001.29,2486.38) U3.1@1001.29,2500.31
  Top Layer L1 w18: Z1.3@981.25,2433.58 981.25,2436.58 1001.29,2456.62 v3(1001.29,2486.38)
  Bottom Layer L6 w18: v3(1001.29,2486.38) 1001.29,2461.75 C18.1@1008.04,2455
NetC19_2: C19.2 C21.1 R3.2 R4.2 U2.4 Z1.1 | length 234.2
  Top Layer L1 w16: C21.1@716.61,2009.51 v3(735.32,2009.51) 760.91,1983.92 R4.2@760.91,1899.06
  Bottom Layer L6 w16: U2.4@735.32,1959.17 v3(735.32,2009.51)
  Bottom Layer L6 w18: v3(970.56,2256.42) v3(991.93,2256.42) ; 981.25,2256.42 C19.2@981.25,2279.2
  other v3: 484.27,1891.18
NetC20_1: C20.1 R1.1 U3.4 U3.6 | length 74.4
  Top Layer L1 w9: v3(893.53,2500.31) U3.6@914.34,2500.31 ; v3(893.53,2551.49) U3.4@914.34,2551.49
  Bottom Layer L6 w16: R1.1@893.53,2467.56 v3(893.53,2500.31)
NetC22_1: C22.1 R2.2 U2.20 | length 113.6
  Top Layer L1 w16: R2.2@600.97,2120 C22.1@600.97,2161.64 607.61,2168.28 v3(607.61,2180.49)
  Bottom Layer L6 w16: v3(607.61,2180.49) U2.20@607.61,2230.83
NetC23_1: C23.1 U2.15 USB.3 | length 366.6
  Top Layer L1 w8: C23.1@474.96,2150.68 479.41,2155.14 v3(479.41,2180.49) 479.41,2212.74 511.66,2245 621.5,2245 648.95,2272.45 648.95,2326.34 USB.3@646,2329.29
  Bottom Layer L6 w16: v3(479.41,2180.49) U2.15@479.41,2230.83
NetC24_1: C24.1 U2.16 USB.2 | length 366.4
  Top Layer L1 w8: C24.1@509.96,2150.68 505.5,2155.14 v3(505.5,2180.49) 505.5,2202.84 522.16,2219.5 632,2219.5 674.54,2262.04 674.54,2326.34 USB.2@677.49,2329.29
  Bottom Layer L6 w16: v3(505.5,2180.49) U2.16@505.5,2230.83
NetC25_2: C25.2 U2.17 | length 85.7
  Top Layer L1 w16: v3(531.34,2180.49) 544.75,2167.08 C25.2@544.75,2150.68
  Bottom Layer L6 w16: v3(531.34,2180.49) U2.17@531.34,2230.83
